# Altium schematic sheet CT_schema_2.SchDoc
size 597 x 347 mm
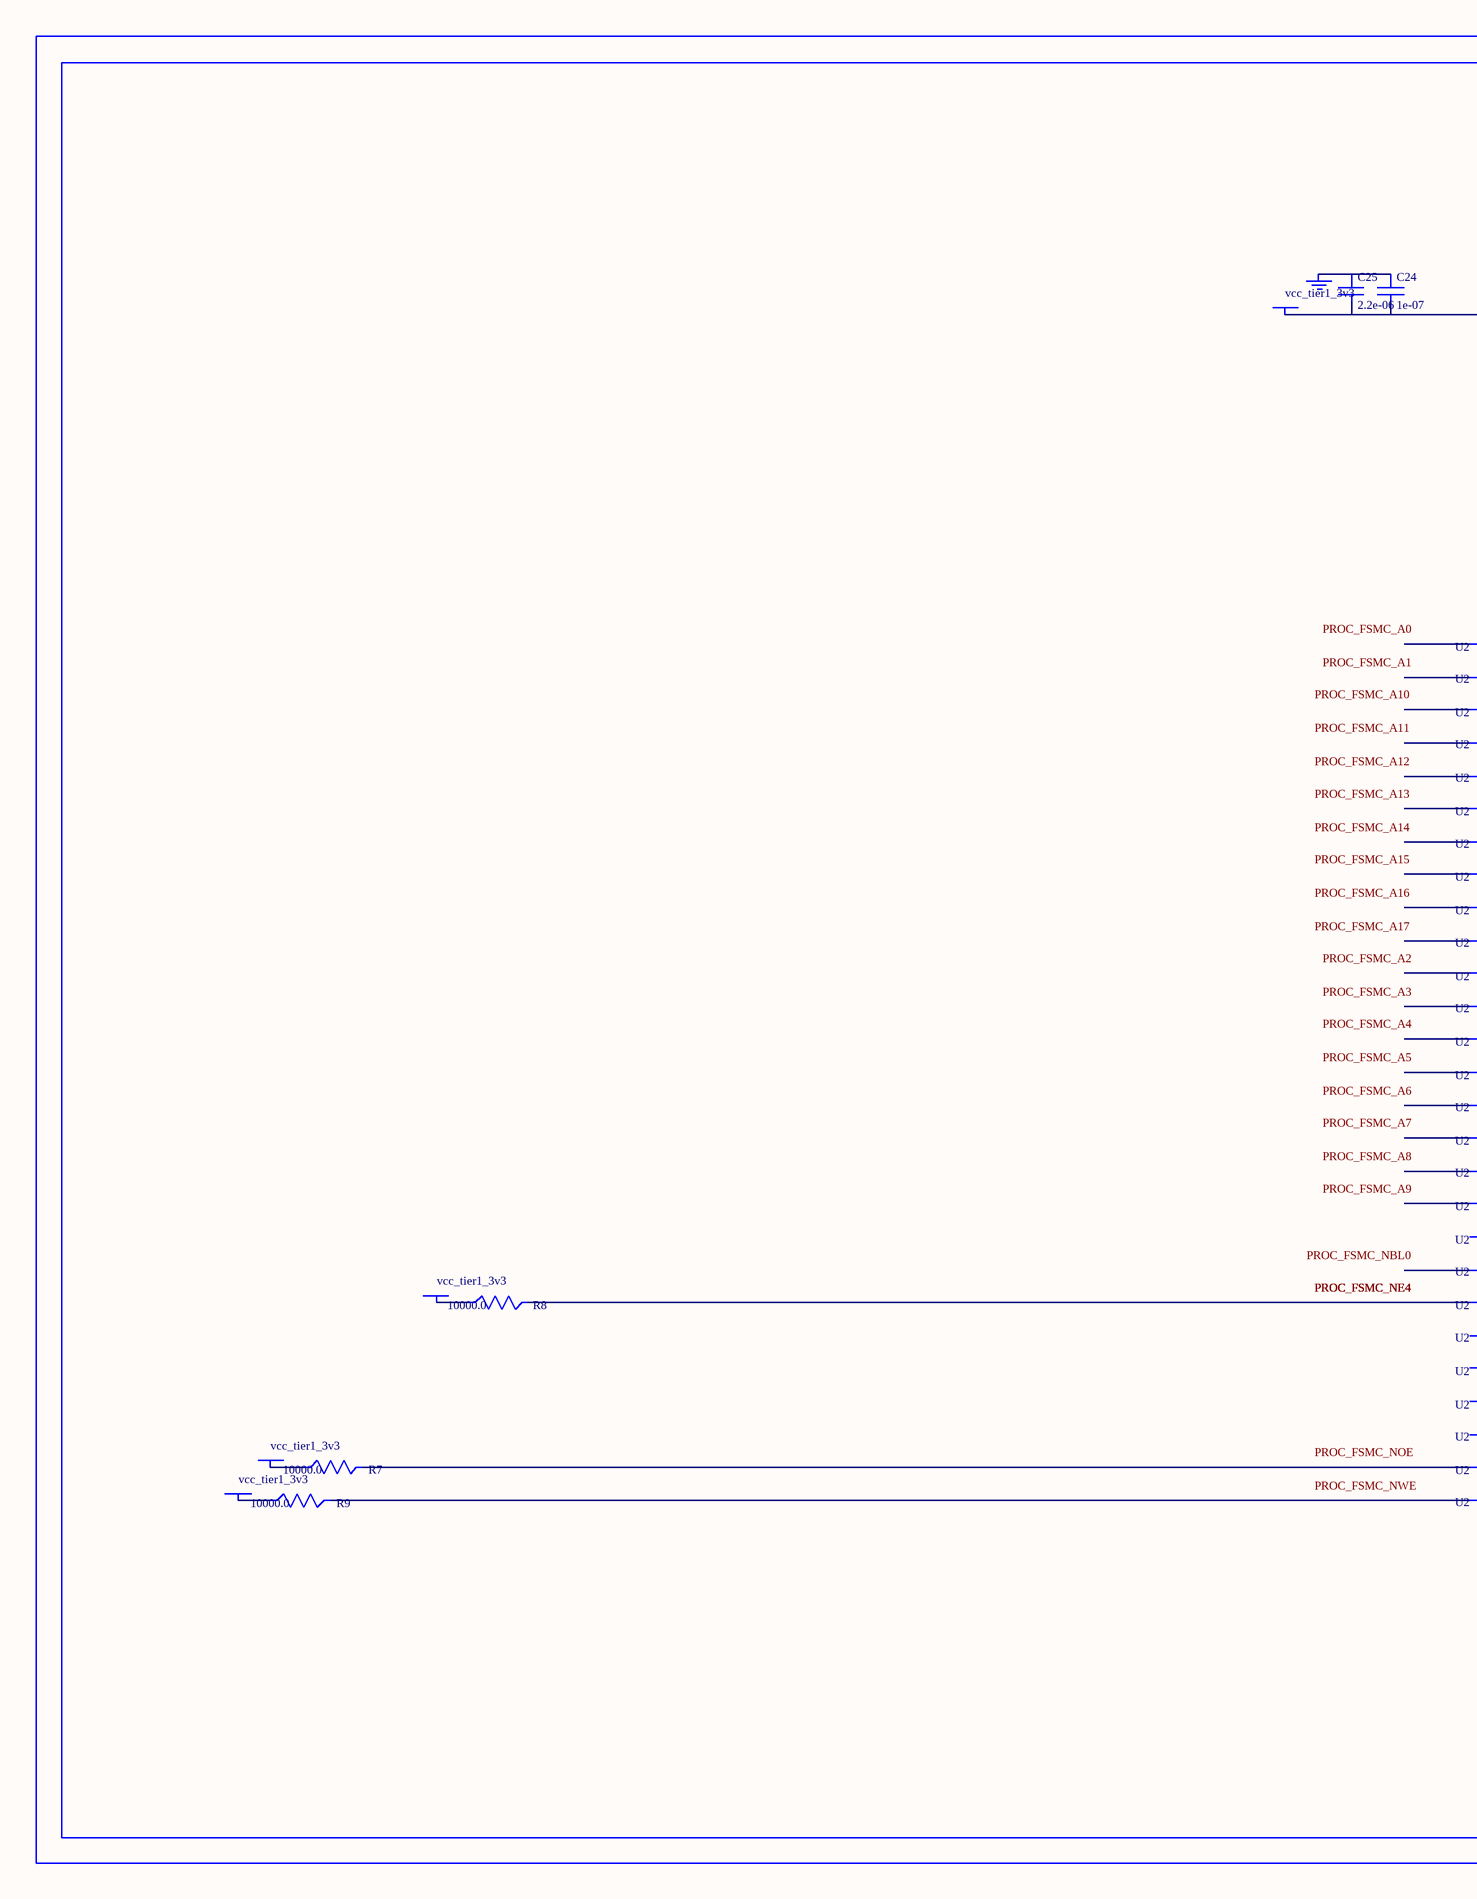
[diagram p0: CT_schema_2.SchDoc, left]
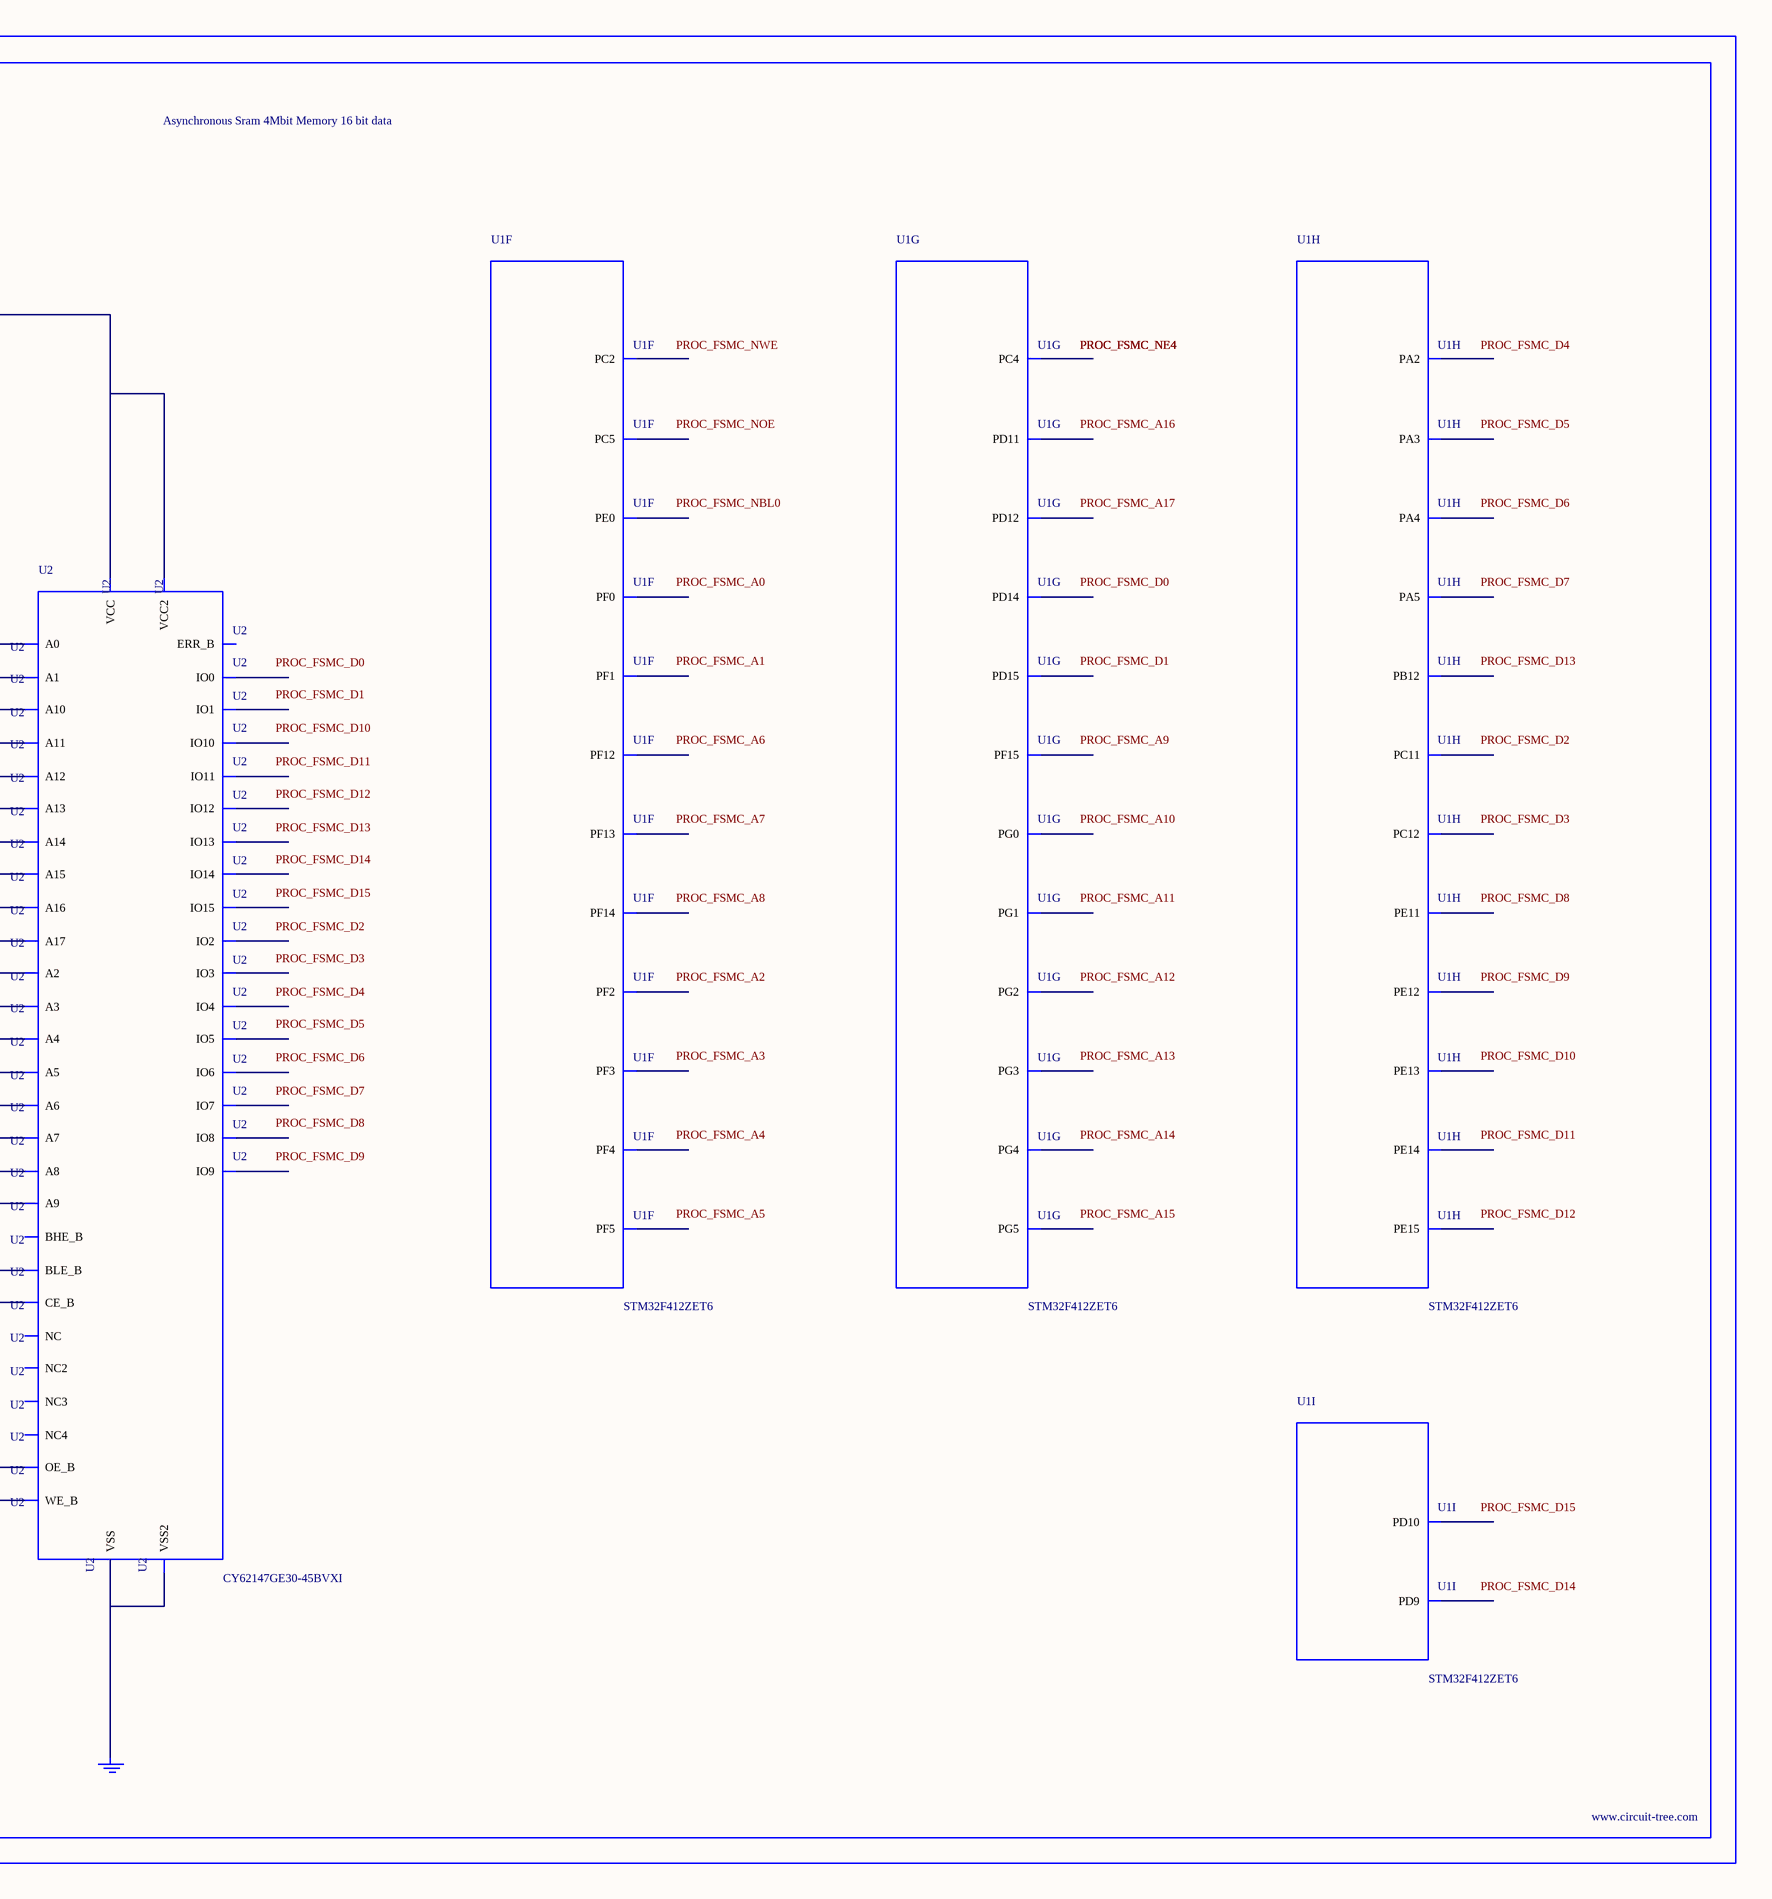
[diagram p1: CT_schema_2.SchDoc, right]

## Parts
BORDER1  (no value)
C24  1e-07  [C0402]
C25  2.2e-06  [C0603]
GND_INSTANCE_1_0  (no value)
GND_INSTANCE_1_1  (no value)
POWER_INSTANCE_1_0  vcc_tier1_3v3
POWER_INSTANCE_1_1  vcc_tier1_3v3
POWER_INSTANCE_1_2  vcc_tier1_3v3
POWER_INSTANCE_1_3  vcc_tier1_3v3
R7  10000.0  [R0603]
R8  10000.0  [R0603]
R9  10000.0  [R0603]
U1  STM32F412ZET6  [LQFP144]  (parts F,G,H,I of 13)
U2  CY62147GE30-45BVXI  [VFBGA48]

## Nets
NetC24_1: C24.1 C25.1 GND_INSTANCE_1_0.0(GND)
NetC24_2: C24.2 C25.2 POWER_INSTANCE_1_0.0(PWR) U2.D6(VCC) U2.E1(VCC2)
NetGND_INSTANCE_1_1_0: GND_INSTANCE_1_1.0(GND) U2.D1(VSS) U2.E6(VSS2)
NetPOWER_INSTANCE_1_1_0: POWER_INSTANCE_1_1.0(PWR) R7.1
NetPOWER_INSTANCE_1_2_0: POWER_INSTANCE_1_2.0(PWR) R8.1
NetPOWER_INSTANCE_1_3_0: POWER_INSTANCE_1_3.0(PWR) R9.1
NetR7_2: R7.2 U2.A2(OE_B)
NetR8_2: R8.2 U2.B5(CE_B)
NetR9_2: R9.2 U2.G5(WE_B)

Not connected (* = marked no-connect by the designer): U1 10(PF0) 11(PF1) 12(PF2) 13(PF3) 14(PF4) 15(PF5) 28(PC2) 36(PA2) 37(PA3) 40(PA4) 41(PA5) 44(PC4) 45(PC5) 50(PF12) 53(PF13) 54(PF14) 55(PF15) 56(PG0) 57(PG1) 64(PE11) 65(PE12) 66(PE13) 67(PE14) 68(PE15) 73(PB12) 78(PD9) 79(PD10) 80(PD11) 81(PD12) 85(PD14) 86(PD15) 87(PG2) 88(PG3) 89(PG4) 90(PG5) 112(PC11) 113(PC12) 141(PE0); U2 A1(BLE_B) A3(A0) A4(A1) A5(A2) A6(NC) B1(IO8) B2(BHE_B) B3(A3) B4(A4) B6(IO0) C1(IO9) C2(IO10) C3(A5) C4(A6) C5(IO1) C6(IO2) D2(IO11) D3(A17) D4(A7) D5(IO3) E2(IO12) E3(ERR_B) E4(A16) E5(IO4) F1(IO14) F2(IO13) F3(A14) F4(A15) F5(IO5) F6(IO6) G1(IO15) G2(NC2) G3(A12) G4(A13) G6(IO7) H1(NC3) H2(A8) H3(A9) H4(A10) H5(A11) H6(NC4)

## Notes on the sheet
- Labels drawn without touching a wire or pin: PROC_FSMC_A0, PROC_FSMC_A1, PROC_FSMC_A2, PROC_FSMC_A3, PROC_FSMC_A4, PROC_FSMC_A5, PROC_FSMC_A6, PROC_FSMC_A7, PROC_FSMC_A8, PROC_FSMC_A9, PROC_FSMC_A10, PROC_FSMC_A11, PROC_FSMC_A12, PROC_FSMC_A13, PROC_FSMC_A14, PROC_FSMC_A15, PROC_FSMC_A16, PROC_FSMC_A17, PROC_FSMC_D0, PROC_FSMC_D1, PROC_FSMC_D2, PROC_FSMC_D3, PROC_FSMC_D4, PROC_FSMC_D5, PROC_FSMC_D6, PROC_FSMC_D7, PROC_FSMC_D8, PROC_FSMC_D9, PROC_FSMC_D10, PROC_FSMC_D11, PROC_FSMC_D12, PROC_FSMC_D13, PROC_FSMC_D14, PROC_FSMC_D15, PROC_FSMC_NBL0, PROC_FSMC_NOE, PROC_FSMC_NWE

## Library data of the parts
BORDER1 = BORDER_PAGE1
C24 = C0402C104K3RACTU
C25 = C0603C225K8RACTU
GND_INSTANCE_1_0 GND_INSTANCE_1_1 = GND
POWER_INSTANCE_1_0-POWER_INSTANCE_1_3 = PWR
R7-R9 = RC0603JR-0710KL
